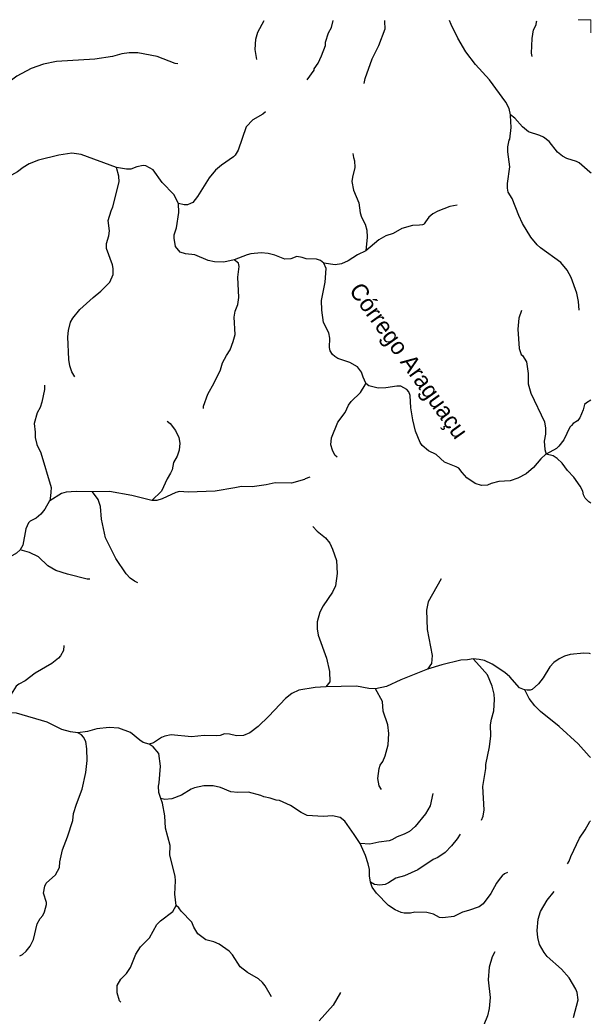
# Model space of a CAD drawing. Extents: x 500 to 555.2, y 9115.7 to 9171.
# Drawn here: x 549.76 to 555.16, y 9161.52 to 9170.95 of the extents above; entities that cross this region are included whole.
import ezdxf
from ezdxf.enums import TextEntityAlignment as Align

# ---------------------------------------------------------------- set-up
doc = ezdxf.new("R2010")
doc.units = 0
doc.header["$LTSCALE"] = 0.064
doc.layers.add('61', color=7, linetype='Continuous')
doc.layers.add('63', color=7, linetype='Continuous', lineweight=13)
doc.layers.add('7', color=7, linetype='Continuous', lineweight=25)

msp = doc.modelspace()

# ---------------------------------------------------------------- linework, layer by layer
at = {"layer": '63'}
msp.add_lwpolyline([(555.1626, 9170.8276), (555.1626, 9170.9508), (555.0412, 9170.9508)], dxfattribs=at)
at = {"layer": '7'}
for points in [[(552.0006, 9170.5751), (551.9838, 9170.6717), (551.9888, 9170.7701), (552.0098, 9170.8346), (552.0681, 9170.9464)], [(552.4762, 9170.3847), (552.5407, 9170.475), (552.5436, 9170.488), (552.5785, 9170.5405), (552.6121, 9170.6093), (552.648, 9170.709), (552.6498, 9170.7417), (552.6777, 9170.8286), (552.7072, 9170.8783), (552.723, 9170.9457)], [(553.0157, 9170.3498), (553.0254, 9170.3956), (553.0921, 9170.5813), (553.1548, 9170.7073), (553.2139, 9170.8652), (553.2108, 9170.9352), (553.2104, 9170.9452)], [(554.3996, 9170.0525), (554.3877, 9170.1116), (554.3572, 9170.1724), (554.2013, 9170.384), (554.0686, 9170.5293), (553.977, 9170.6497), (553.9025, 9170.7771), (553.8389, 9170.909), (553.8218, 9170.9445)], [(554.6067, 9170.6036), (554.601, 9170.6363), (554.6063, 9170.7741), (554.6194, 9170.8569), (554.6435, 9170.9054), (554.6476, 9170.932), (554.6494, 9170.9435)], [(551.2528, 9170.5351), (551.2266, 9170.5381), (551.0559, 9170.6053), (550.8716, 9170.6399), (550.7918, 9170.6382), (550.7222, 9170.6297), (550.6327, 9170.604), (550.4655, 9170.5793), (550.1025, 9170.5561), (549.9793, 9170.5317), (549.8639, 9170.4921), (549.7285, 9170.4197), (549.6652, 9170.3704)], [(552.08, 9170.0812), (552.0569, 9170.0583), (551.9619, 9170.0059), (551.8973, 9169.9382), (551.8215, 9169.7191), (551.7928, 9169.6692), (551.7784, 9169.6541), (551.6641, 9169.5751), (551.6077, 9169.5289), (551.5478, 9169.4546), (551.4384, 9169.2782), (551.3929, 9169.2231), (551.3712, 9169.2113), (551.3442, 9169.2), (551.3112, 9169.1999), (551.258, 9169.2141)], [(555.0506, 9168.2041), (555.0445, 9168.2861), (555.0282, 9168.3643), (554.9756, 9168.5125), (554.9359, 9168.582), (554.8783, 9168.6539), (554.6854, 9168.7915), (554.6538, 9168.8213), (554.5943, 9168.8935), (554.5161, 9169.0248), (554.4803, 9169.0998), (554.4182, 9169.2598), (554.3802, 9169.3186), (554.3721, 9169.3576), (554.372, 9169.4015), (554.395, 9169.5602), (554.3754, 9169.702), (554.3753, 9169.7493), (554.3887, 9169.8135), (554.3947, 9169.8205), (554.4065, 9169.933), (554.401, 9170.0456), (554.3996, 9170.0525)], [(555.1638, 9169.4996), (555.153, 9169.509), (555.0522, 9169.5963), (555.0263, 9169.6113), (554.9331, 9169.6394), (554.8932, 9169.6606), (554.8469, 9169.6978), (554.7668, 9169.7987), (554.712, 9169.8407), (554.6791, 9169.856), (554.5727, 9169.8897), (554.5157, 9169.9387), (554.4413, 9170.0211), (554.3996, 9170.0525)], [(550.6721, 9169.5541), (550.6718, 9169.5542), (550.3369, 9169.677), (550.249, 9169.6886), (550.1232, 9169.6711), (549.9334, 9169.623), (549.8449, 9169.5885), (549.7858, 9169.554), (549.7326, 9169.5111), (549.6756, 9169.4809), (549.5765, 9169.4606)], [(552.909, 9169.6853), (552.9133, 9169.6468), (552.9238, 9169.6169), (552.9269, 9169.5524), (552.904, 9169.4606), (552.8992, 9169.4202), (552.914, 9169.3387), (552.9663, 9169.2205), (552.9779, 9169.1234), (552.9892, 9169.0842), (553.0253, 9169.0177), (553.0399, 9168.9593), (553.0433, 9168.8948), (553.0309, 9168.7653)], [(550.2745, 9167.5711), (550.2488, 9167.6201), (550.2303, 9167.676), (550.2188, 9167.735), (550.209, 9167.9515), (550.2153, 9168.0092), (550.2354, 9168.0899), (550.2565, 9168.127), (550.3242, 9168.2095), (550.4497, 9168.3232), (550.5238, 9168.3813), (550.6064, 9168.4677), (550.6402, 9168.5404), (550.6386, 9168.5972), (550.632, 9168.6306), (550.5765, 9168.7881), (550.5763, 9168.8343), (550.5992, 9168.9062), (550.6058, 9168.9548), (550.5914, 9169.0511), (550.6186, 9169.1444), (550.6371, 9169.1807), (550.6944, 9169.4179), (550.6941, 9169.4726), (550.6721, 9169.5541)], [(551.258, 9169.2141), (551.2128, 9169.2965), (551.1039, 9169.4118), (551.0191, 9169.531), (550.9496, 9169.5705), (550.9216, 9169.5716), (550.8636, 9169.5584), (550.8066, 9169.538), (550.7653, 9169.5364), (550.6721, 9169.5541)], [(551.7842, 9168.6793), (551.6877, 9168.657), (551.5973, 9168.6601), (551.537, 9168.6719), (551.4123, 9168.7258), (551.3225, 9168.737), (551.2736, 9168.7505), (551.2295, 9168.804), (551.2162, 9168.8852), (551.2163, 9168.9174), (551.239, 9168.9817), (551.2619, 9169.1286), (551.258, 9169.2141)], [(553.897, 9169.1964), (553.828, 9169.1834), (553.7138, 9169.1412), (553.665, 9169.1161), (553.627, 9169.0845), (553.5951, 9169.0385), (553.5848, 9169.0206), (553.5771, 9169.0129), (553.569, 9169.0096), (553.5387, 9169.0077), (553.4731, 9169.0029), (553.3719, 9168.9752), (553.291, 9168.9292), (553.2191, 9168.9054), (553.1544, 9168.8696), (553.0309, 9168.7653)], [(552.6334, 9168.6466), (552.6331, 9168.6473), (552.6017, 9168.6729), (552.5638, 9168.6863), (552.4667, 9168.6897), (552.4299, 9168.7027), (552.3795, 9168.7094), (552.3216, 9168.6897), (552.2649, 9168.6848), (552.1701, 9168.7226), (552.1051, 9168.7388), (552.0402, 9168.7453), (551.9418, 9168.7356), (551.909, 9168.7276), (551.7842, 9168.6793)], [(553.0309, 9168.7653), (552.9516, 9168.7273), (552.8635, 9168.6703), (552.802, 9168.6426), (552.7401, 9168.6307), (552.6334, 9168.6466)], [(551.4934, 9167.2721), (551.495, 9167.2936), (551.5342, 9167.408), (551.5966, 9167.5136), (551.6551, 9167.6388), (551.6755, 9167.7049), (551.7105, 9167.7738), (551.7458, 9167.8286), (551.7767, 9167.9045), (551.7933, 9167.973), (551.7853, 9168.1359), (551.7948, 9168.1929), (551.818, 9168.2567), (551.8295, 9168.3222), (551.8198, 9168.514), (551.8329, 9168.616), (551.8241, 9168.6489), (551.7842, 9168.6793)], [(553.0307, 9167.5105), (553.0048, 9167.5671), (552.9907, 9167.6147), (552.9515, 9167.6676), (552.8812, 9167.706), (552.7652, 9167.7462), (552.7367, 9167.7629), (552.7155, 9167.7842), (552.6946, 9167.8192), (552.686, 9167.8492), (552.6905, 9167.9391), (552.6822, 9167.9891), (552.6302, 9168.086), (552.6136, 9168.2035), (552.6121, 9168.2934), (552.6463, 9168.4692), (552.656, 9168.5962), (552.6334, 9168.6466)], [(554.5039, 9168.2004), (554.4803, 9168.1285), (554.4688, 9168.0243), (554.4821, 9167.8394), (554.5026, 9167.7837), (554.5161, 9167.7725), (554.5524, 9167.7146), (554.5688, 9167.6044), (554.5672, 9167.5059), (554.595, 9167.4169), (554.723, 9167.1445), (554.7327, 9167.0869), (554.7328, 9167.0271), (554.7199, 9166.9631), (554.725, 9166.8835), (554.7372, 9166.84)], [(549.9895, 9167.4918), (549.9894, 9167.4513), (549.9646, 9167.3322), (549.9468, 9167.2802), (549.9188, 9167.2298), (549.8908, 9167.1309), (549.9005, 9167.0467), (549.9006, 9166.9975), (549.917, 9166.9313), (549.9529, 9166.8514), (550.0512, 9166.525), (550.0501, 9166.4794), (550.0462, 9166.4444), (550.0381, 9166.3976)], [(552.7586, 9166.811), (552.7381, 9166.829), (552.7155, 9166.8783), (552.7006, 9166.9286), (552.7054, 9166.993), (552.7652, 9167.1424), (552.8343, 9167.2337), (552.8663, 9167.3036), (552.8937, 9167.3393), (552.9794, 9167.4218), (553.0262, 9167.4944), (553.0307, 9167.5105)], [(554.7372, 9166.84), (554.7351, 9166.8389), (554.6868, 9166.7948), (554.6175, 9166.7142), (554.5499, 9166.6537), (554.469, 9166.6108), (554.3989, 9166.5854), (554.2894, 9166.58), (554.2185, 9166.5624), (554.1817, 9166.5443), (554.1264, 9166.5412), (554.0664, 9166.5609), (553.9872, 9166.6143), (553.9437, 9166.6671), (553.9104, 9166.7081), (553.8853, 9166.7209), (553.7772, 9166.7637), (553.6967, 9166.8372), (553.6251, 9166.8694), (553.5652, 9166.9198), (553.5463, 9166.9491), (553.5009, 9167.0566), (553.4748, 9167.1643), (553.4572, 9167.2794), (553.4517, 9167.3938), (553.4382, 9167.4304), (553.4206, 9167.4526), (553.3633, 9167.4824), (553.326, 9167.4838), (553.2199, 9167.4676), (553.1483, 9167.4628), (553.0607, 9167.4854), (553.0322, 9167.5072), (553.0307, 9167.5105)], [(555.1614, 9167.3512), (555.1205, 9167.326), (555.1025, 9167.308), (555.0897, 9167.2593), (555.0572, 9167.1834), (555.0342, 9167.1541), (554.9933, 9167.1291), (554.9769, 9167.1106), (554.9628, 9167.0941), (554.906, 9166.976), (554.8585, 9166.9143), (554.8357, 9166.8933), (554.7372, 9166.84)], [(551.1495, 9167.1524), (551.1779, 9167.1283), (551.2291, 9167.0625), (551.2622, 9166.9964), (551.2703, 9166.942), (551.2635, 9166.8783), (551.2453, 9166.8192), (551.2092, 9166.7594), (551.1962, 9166.6919), (551.183, 9166.6585), (551.1488, 9166.6067), (551.0959, 9166.4876), (551.0045, 9166.4005)], [(555.1602, 9166.3756), (555.1435, 9166.389), (555.1077, 9166.4235), (555.0906, 9166.4532), (555.0872, 9166.4878), (555.0601, 9166.5356), (554.9995, 9166.62), (554.9405, 9166.6856), (554.8903, 9166.7541), (554.8436, 9166.7978), (554.8036, 9166.8233), (554.7372, 9166.84)], [(552.5005, 9166.6217), (552.4567, 9166.6048), (552.4515, 9166.5979), (552.3261, 9166.5652), (552.1713, 9166.5688), (552.0881, 9166.5474), (551.9546, 9166.529), (551.8531, 9166.5343), (551.7921, 9166.5193), (551.6059, 9166.4884), (551.3479, 9166.4803), (551.2665, 9166.4847), (551.2312, 9166.4765), (551.1029, 9166.4168), (551.0513, 9166.4014), (551.0045, 9166.4005)], [(550.4444, 9166.4823), (550.4402, 9166.4822), (550.2877, 9166.485), (550.1936, 9166.478), (550.1514, 9166.4659), (550.0381, 9166.3976)], [(551.0045, 9166.4005), (550.8158, 9166.449), (550.6033, 9166.4866), (550.4444, 9166.4823)], [(550.8716, 9165.6219), (550.8409, 9165.6358), (550.8, 9165.6663), (550.763, 9165.7065), (550.6634, 9165.852), (550.5668, 9166.0483), (550.5275, 9166.2247), (550.5185, 9166.3453), (550.496, 9166.4096), (550.4444, 9166.4823)], [(550.0381, 9166.3976), (550.0368, 9166.3968), (549.9926, 9166.3189), (549.9547, 9166.2703), (549.9109, 9166.2345), (549.853, 9166.206), (549.8387, 9166.1903), (549.8113, 9166.1317), (549.7825, 9165.9773), (549.7573, 9165.9346)], [(552.5301, 9166.1537), (552.5717, 9166.1103), (552.648, 9166.0456), (552.6889, 9165.996), (552.7165, 9165.9407), (552.7546, 9165.8322), (552.7611, 9165.7085), (552.7433, 9165.5935), (552.7155, 9165.5313), (552.6261, 9165.4039), (552.5943, 9165.344), (552.5695, 9165.2523), (552.5709, 9165.1867), (552.5794, 9165.1263), (552.6596, 9164.9065), (552.6858, 9164.7819), (552.689, 9164.683), (552.6511, 9164.6366)], [(549.7573, 9165.9346), (549.724, 9165.9017), (549.6211, 9165.8418), (549.5555, 9165.8174), (549.3349, 9165.7662), (549.2773, 9165.7469), (549.1881, 9165.7074), (549.1281, 9165.6978), (549.0655, 9165.7041), (549.0249, 9165.7143), (548.9676, 9165.7533), (548.871, 9165.8351), (548.8312, 9165.859), (548.7664, 9165.8782), (548.7065, 9165.8574), (548.6731, 9165.8334), (548.6299, 9165.7887)], [(550.4183, 9165.6568), (550.3936, 9165.6571), (550.2057, 9165.7027), (550.0953, 9165.7391), (550.0214, 9165.7807), (549.9321, 9165.8663), (549.8476, 9165.9095), (549.7573, 9165.9346)], [(553.7443, 9165.66), (553.6223, 9165.4397), (553.605, 9165.3611), (553.6125, 9165.1802), (553.6584, 9164.9334), (553.6522, 9164.8574), (553.6148, 9164.8045)], [(550.1713, 9165.0281), (550.1674, 9164.9815), (550.1413, 9164.9297), (550.1199, 9164.9068), (550.0573, 9164.8586), (549.9007, 9164.7644), (549.8052, 9164.6933), (549.7465, 9164.6611), (549.7218, 9164.6413), (549.5592, 9164.3893)], [(555.1586, 9164.9492), (555.1484, 9164.9504), (555.0964, 9164.9563), (554.9665, 9164.9433), (554.9134, 9164.9268), (554.8603, 9164.9002), (554.81, 9164.8661), (554.7718, 9164.8246), (554.7098, 9164.7202), (554.6667, 9164.6638), (554.607, 9164.6108), (554.5865, 9164.6056), (554.559, 9164.6033), (554.5356, 9164.6083)], [(554.0463, 9164.9007), (553.9933, 9164.8918), (553.9298, 9164.8875), (553.752, 9164.8448), (553.6148, 9164.8045)], [(554.1276, 9163.3754), (554.1418, 9163.413), (554.1505, 9163.4702), (554.1391, 9163.6939), (554.1669, 9163.8645), (554.1671, 9163.9), (554.203, 9164.0673), (554.2145, 9164.1717), (554.2113, 9164.278), (554.2195, 9164.3297), (554.2439, 9164.4085), (554.2506, 9164.5149), (554.2455, 9164.5673), (554.2278, 9164.6441), (554.182, 9164.7491), (554.1084, 9164.8344), (554.0463, 9164.9007)], [(554.5356, 9164.6083), (554.5337, 9164.6084), (554.4872, 9164.6268), (554.3938, 9164.7311), (554.3474, 9164.771), (554.2271, 9164.8501), (554.1538, 9164.8867), (554.1027, 9164.8956), (554.0463, 9164.9007)], [(553.6148, 9164.8045), (553.3638, 9164.7024), (553.2277, 9164.6384), (553.1229, 9164.6166)], [(552.6511, 9164.6366), (552.5513, 9164.6315), (552.3965, 9164.605), (552.3316, 9164.5741), (552.2712, 9164.527), (552.1138, 9164.3597), (552.0105, 9164.2616), (551.9328, 9164.2019), (551.8728, 9164.1758), (551.806, 9164.1724), (551.7417, 9164.1884), (551.6919, 9164.1904), (551.6505, 9164.176), (551.6203, 9164.1723), (551.5001, 9164.1755), (551.382, 9164.1642), (551.1883, 9164.182), (551.1276, 9164.1706), (551.0975, 9164.1571), (551.0219, 9164.1049), (550.9805, 9164.0946)], [(553.1229, 9164.6166), (553.0589, 9164.6191), (552.943, 9164.6413), (552.6511, 9164.6366)], [(553.1803, 9163.6644), (553.1578, 9163.6995), (553.1452, 9163.7699), (553.1582, 9163.8639), (553.1674, 9163.8948), (553.1927, 9163.9301), (553.2137, 9163.9815), (553.2434, 9164.0858), (553.2483, 9164.1949), (553.2398, 9164.275), (553.1958, 9164.4064), (553.1905, 9164.4982), (553.1229, 9164.6166)], [(555.1575, 9163.9666), (555.1451, 9163.9804), (555.04, 9164.098), (554.8619, 9164.2613), (554.6864, 9164.4041), (554.6316, 9164.4555), (554.5771, 9164.5267), (554.5356, 9164.6083)], [(550.3044, 9164.2014), (550.2335, 9164.2113), (550.1539, 9164.2329), (550.0136, 9164.3029), (549.7241, 9164.3871), (549.6114, 9164.3886)], [(549.7565, 9162.0889), (549.7796, 9162.1011), (549.8157, 9162.1338), (549.8539, 9162.1794), (549.8841, 9162.2433), (549.9185, 9162.3937), (549.9479, 9162.4429), (549.9727, 9162.4697), (549.9902, 9162.5045), (550.0089, 9162.5756), (550.0086, 9162.5959), (549.9793, 9162.6835), (549.9906, 9162.748), (550.0049, 9162.7772), (550.0944, 9162.856), (550.1315, 9162.9268), (550.1355, 9162.9801), (550.1585, 9163.0941), (550.2057, 9163.2168), (550.2559, 9163.3699), (550.2634, 9163.438), (550.2907, 9163.5248), (550.3468, 9163.666), (550.3791, 9163.8262), (550.3943, 9163.9395), (550.3912, 9164.0486), (550.3796, 9164.1192), (550.3582, 9164.1602), (550.3394, 9164.1809), (550.3044, 9164.2014)], [(550.9805, 9164.0946), (550.9225, 9164.1104), (550.89, 9164.1301), (550.8027, 9164.2047), (550.694, 9164.2439), (550.602, 9164.2525), (550.4839, 9164.2377), (550.3951, 9164.2148), (550.3044, 9164.2014)], [(551.0893, 9163.5779), (551.0702, 9163.6348), (551.0685, 9163.696), (551.075, 9163.7262), (551.0865, 9163.8863), (551.0719, 9164.0053), (551.0179, 9164.0686), (550.9805, 9164.0946)], [(552.976, 9163.1518), (552.9203, 9163.2387), (552.8315, 9163.3651), (552.7882, 9163.3985), (552.716, 9163.416), (552.6267, 9163.4096), (552.4766, 9163.4183), (552.4198, 9163.4465), (552.3167, 9163.5112), (552.2134, 9163.5587), (552.1824, 9163.5625), (552.1248, 9163.5834), (552.0658, 9163.595), (552.0356, 9163.6081), (551.9196, 9163.6405), (551.8191, 9163.636), (551.7542, 9163.641), (551.6546, 9163.6816), (551.5868, 9163.6982), (551.4968, 9163.6997), (551.409, 9163.6799), (551.3777, 9163.6673), (551.2869, 9163.6107), (551.1931, 9163.5753), (551.1285, 9163.5682), (551.0893, 9163.5779)], [(553.6646, 9163.6271), (553.6419, 9163.5097), (553.5956, 9163.4329), (553.4998, 9163.3137), (553.4431, 9163.2665), (553.395, 9163.2409), (553.3265, 9163.2172), (553.2762, 9163.1866), (553.2526, 9163.1788), (553.1537, 9163.1666), (553.0702, 9163.1472), (552.976, 9163.1518)], [(551.2347, 9162.5667), (551.2244, 9162.6725), (551.2307, 9162.8004), (551.2261, 9162.8442), (551.1753, 9163.0432), (551.1779, 9163.1349), (551.1344, 9163.2975), (551.1273, 9163.4152), (551.1048, 9163.5344), (551.0893, 9163.5779)], [(554.9406, 9162.9591), (554.9576, 9162.987), (554.9711, 9163.0311), (555.0544, 9163.2045), (555.1084, 9163.2817), (555.1529, 9163.3604), (555.1568, 9163.3672)], [(553.9245, 9163.2415), (553.895, 9163.1984), (553.8431, 9163.1316), (553.782, 9163.0672), (553.7137, 9163.0198), (553.6683, 9163.0005), (553.5234, 9162.9025), (553.3977, 9162.846), (553.3168, 9162.8237), (553.247, 9162.7793), (553.2151, 9162.7653), (553.1644, 9162.76), (553.1131, 9162.7651), (553.076, 9162.7853)], [(553.076, 9162.7853), (553.0756, 9162.7864), (553.0661, 9162.848), (553.0647, 9162.906), (553.0547, 9162.9592), (553.0284, 9163.0378), (552.976, 9163.1518)], [(554.3735, 9162.8788), (554.3443, 9162.8646), (554.3232, 9162.8472), (554.3027, 9162.8241), (554.269, 9162.7785), (554.2145, 9162.6797), (554.1407, 9162.5829), (554.103, 9162.5536), (554.004, 9162.5172), (553.9455, 9162.5024), (553.8631, 9162.4609), (553.7606, 9162.4484), (553.7279, 9162.4537), (553.6709, 9162.4844), (553.6076, 9162.4991), (553.4961, 9162.5024), (553.4546, 9162.4941), (553.3951, 9162.4927), (553.3642, 9162.4994), (553.3085, 9162.5242), (553.2462, 9162.5653), (553.1324, 9162.6824), (553.0924, 9162.7403), (553.076, 9162.7853)], [(554.9985, 9161.5046), (555.0411, 9161.6725), (555.0313, 9161.7414), (555.0196, 9161.7747), (554.9559, 9161.8824), (554.885, 9161.9617), (554.7493, 9162.0843), (554.7186, 9162.1198), (554.6761, 9162.196), (554.6608, 9162.2615), (554.6525, 9162.3293), (554.6622, 9162.4354), (554.6852, 9162.5084), (554.7483, 9162.6159), (554.8133, 9162.6977)], [(550.7106, 9161.6505), (550.6983, 9161.6637), (550.6765, 9161.7381), (550.6781, 9161.8093), (550.7122, 9161.8688), (550.7666, 9161.9235), (550.8043, 9161.9777), (550.8547, 9162.1043), (550.8965, 9162.1759), (550.9823, 9162.2592), (551.0539, 9162.3845), (551.0887, 9162.4208), (551.2055, 9162.5083), (551.2347, 9162.5667)], [(552.1377, 9161.7002), (552.0795, 9161.8059), (552.053, 9161.8377), (552.0137, 9161.8705), (551.9111, 9161.932), (551.8428, 9161.9842), (551.7704, 9162.099), (551.7376, 9162.1334), (551.6431, 9162.2003), (551.5928, 9162.2205), (551.5159, 9162.2419), (551.4418, 9162.2966), (551.4034, 9162.3609), (551.3829, 9162.4094), (551.2831, 9162.5109), (551.2603, 9162.5451), (551.2347, 9162.5667)], [(554.2526, 9162.1267), (554.2261, 9162.0809), (554.1983, 9161.9809), (554.19, 9161.8627), (554.208, 9161.6952), (554.1993, 9161.5919), (554.1823, 9161.5215), (554.1475, 9161.4369), (554.1176, 9161.3438), (554.0981, 9161.2224)], [(552.7925, 9161.7409), (552.7226, 9161.6211), (552.5891, 9161.474)]]:
    msp.add_lwpolyline(points, dxfattribs=at)

# ---------------------------------------------------------------- texts
at = {"layer": '61'}
msp.add_text('Córrego Araguaçu', height=0.16, rotation=305.538, dxfattribs=at).set_placement((553.3742, 9167.6782), align=Align.CENTER)

doc.saveas('drawing.dxf')
